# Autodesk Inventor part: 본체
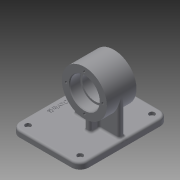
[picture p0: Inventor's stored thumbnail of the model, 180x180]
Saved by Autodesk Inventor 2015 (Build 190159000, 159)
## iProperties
Created: 2019-09
Part Number: 본체
Material: 일반
Document SubType Name: Modeling
Designer: 1010101
Density: 1 g/cm^3
Appearance: 기본값
Author: 1010101
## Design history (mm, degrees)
sketch "스케치1"
  geometry: C1 r 32 at (0, 0); 1 further point
  constraints: 1 centre point, 1 coincident
  dimensions: "d0" = 64 diameter of C1
extrude "돌출1" new body sketch "스케치1" stored distance "d1" = 42; taper "d2" = 0 deg
sketch "스케치2"
  geometry: C1 r 32 at (0, 0) reference; C2 r 21 at (0, 0)
  constraints: 1 centre point, 1 coincident
  dimensions: "d3" = 42 diameter of C2
extrude "돌출2" cut sketch "스케치2" distance "d4" = 15; taper "d5" = 0 deg
sketch "스케치3"
  geometry: C1 r 21 at (0, 0) reference; C2 r 18 at (0, 0)
  constraints: 1 centre point, 1 coincident
  dimensions: "d6" = 36 diameter of C2
extrude "돌출3" cut sketch "스케치3" stored distance "d7" = 15; taper "d8" = 0 deg
sketch "스케치4"
  geometry: C1 r 18 at (0, 0) reference; C2 r 32 at (0, 0) reference; C3 r 21 at (0, 0)
  constraints: 1 centre point, 1 coincident
  dimensions: "d9" = 42 diameter of C3
extrude "돌출4" cut sketch "스케치4" distance "d10" = 15; taper "d11" = 0 deg
sketch "스케치5" dims "d12" = 52
  geometry: C1 r 21 at (0, 0) reference; C2 r 32 at (0, 0) reference; 2 further points
  constraints: 2 vertical alignment, 1 coincident, 2 other
hole "구멍1" sketch "스케치5" at (0, -26) diameter "d13" = 3.242; stored, may be unused: countersink angle "d17" = 90 deg, drill point angle "d19" = 118 deg; dims "d14" = 8, "d15" = 4, "d16" = 2, "d18" = 10
sketch "스케치6" dims "d23" = 52
  geometry: C1 r 32 at (0, 0) reference; 2 further points
  constraints: 1 coincident, 1 vertical alignment, 2 other
hole "구멍2" sketch "스케치6" at (0, 26) diameter "d24" = 3.242; stored, may be unused: countersink angle "d28" = 90 deg, drill point angle "d30" = 118 deg; dims "d25" = 8, "d26" = 4, "d27" = 2, "d29" = 10
node "작업 평면3"
sketch "스케치11"
  geometry: L1 (-62, -63)-(36, -63); L2 (36, -63)-(36, 63); L3 (36, 63)-(-62, 63); L4 (-62, 63)-(-62, -63); 1 further point
  constraints: 8 end point, 2 parallel, 1 horizontal, 1 perpendicular
  dimensions: "d47" = 126 distance of L1.end L2.end; "d48" = 36 distance from line of L2 point (0, 0); "d49" = 98 distance of L1.start L1.end; "d53" = 63 distance from line of L3 point (0, 0)
extrude "돌출6" join sketch "스케치11" distance "d51" = 9; taper "d52" = 0 deg
fillet "모깎기1" dims "d54" = 12
sketch "스케치12"
  geometry: L1 (-32, 4)-(32, 4); L2 (32, 4)-(32, -4); L3 (32, -4)-(-32, -4); L4 (-32, -4)-(-32, 4); 1 further point
  constraints: 8 end point, 2 parallel, 1 horizontal, 1 perpendicular
  dimensions: "d55" = 8 distance of L1.end L2.end; "d56" = 4 distance from line of L1 point (0, 0); "d57" = 64 distance of L1.start L1.end; "d58" = 32 distance from line of point (0, 0) L2
extrude "돌출7" join sketch "스케치12" stored distance "d59" = 9; taper "d60" = 0 deg
sketch "스케치13"
  geometry: L1 (-4, -17)-(4, -17); L2 (4, -17)-(4, 17); L3 (4, 17)-(-4, 17); L4 (-4, 17)-(-4, -17); L5 (-4, -17)-(4, 17); L6 (4, -17)-(-4, 17); 1 further point
  constraints: 12 end point, 2 midpoint, 2 parallel, 1 horizontal, 1 perpendicular
  dimensions: "d61" = 8 distance of L2.end L3.end; "d62" = 34 distance of L1.end L2.end
extrude "돌출8" join sketch "스케치13" stored distance "d63" = 9; taper "d64" = 0 deg
sketch "스케치14"
  geometry: A1 r 12 centre (-50, 51) between (-50, 63) and (-62, 51) reference; A2 r 12 centre (-50, -51) between (-62, -51) and (-50, -63) reference; A3 r 12 centre (24, -51) between (24, -63) and (36, -51) reference; A4 r 12 centre (24, 51) between (36, 51) and (24, 63) reference; 1 further point
hole "구멍3" sketch "스케치14" at (-50, 51), (-50, -51), (24, 51), (24, -51) diameter "d65" = 4.5; stored, may be unused: countersink angle "d69" = 90 deg, drill point angle "d71" = 118 deg; dims "d66" = 4.5, "d67" = 8, "d68" = 4.4, "d70" = 11.8
sketch "스케치15"
  geometry: L1 (-62, 51)-(-62, -51) reference; L2 (24, 63)-(-50, 63) reference; 2 further points
  constraints: 1 other
  dimensions: "d72" = 63 distance from line of L2 point (-52, 0); "d73" = 10 distance from line of L1 point (-52, 0)
feature "엠보싱1" sketch "스케치15" dims "d74" = 0.5, "d75" = 0
fillet "모깎기2" dims "d76" = 3
fillet "모깎기3" dims "d77" = 3
fillet "모깎기4" dims "d78" = 3
fillet "모깎기5" dims "d79" = 0.3
chamfer "모따기1" distance "d80" = 1; stored, may be unused: second distance "d81" = 2, angle "d82" = 45 deg
node "솔리드1"
pattern_circular "원형 패턴1" dims angle "d21" = 360 deg
pattern_circular "원형 패턴2" dims angle "d32" = 360 deg
other parameters: "d46" = -59
